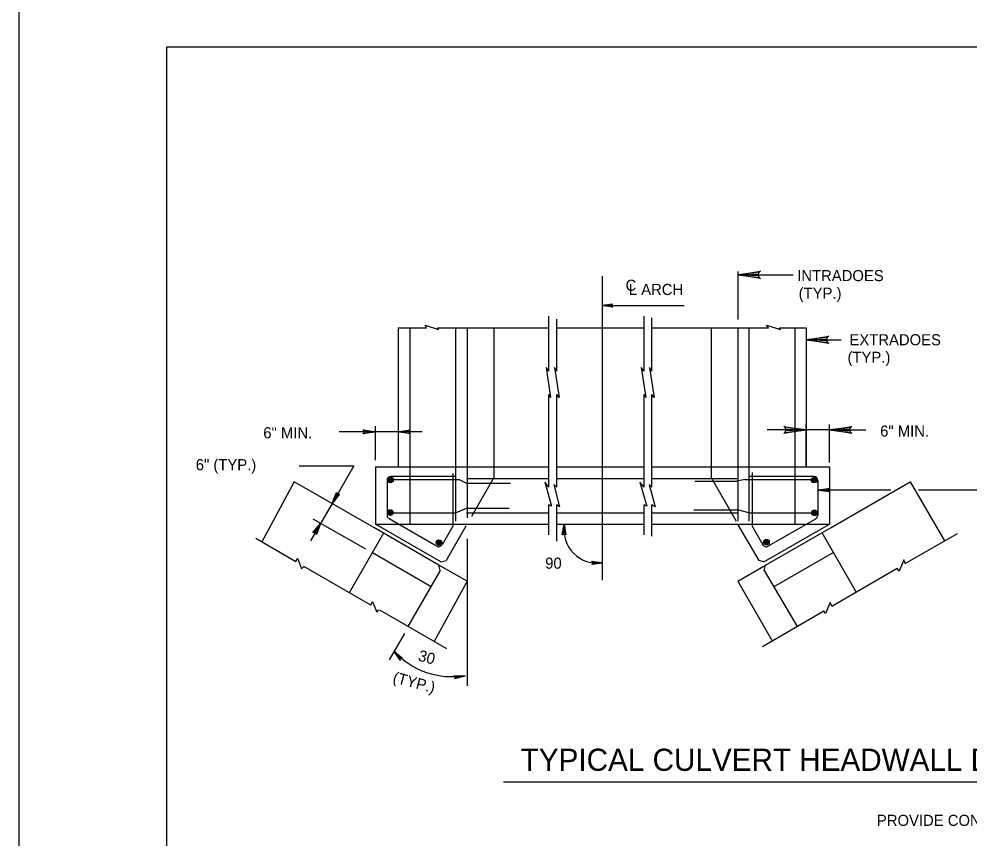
# Model space of a CAD drawing. Extents: x 639028 to 639883, y 298843 to 300031.
# Drawn here: x 639027.7 to 639285, y 299207.9 to 299429.6 of the extents above; entities that cross this region are included whole.
import ezdxf

# ---------------------------------------------------------------- set-up
doc = ezdxf.new("R2010")
doc.units = 0
for name, color, linetype in [('2', 7, 'Continuous'), ('52', 7, 'Continuous'), ('53', 7, 'Continuous'), ('PLT-BNDY', 7, 'Continuous')]:
    doc.layers.add(name, color=color, linetype=linetype)

msp = doc.modelspace()

# ---------------------------------------------------------------- linework, layer by layer
at = {"layer": '2'}
for p, q in [((639067.74, 298858.08), (639067.74, 299422.08)), ((639067.74, 299422.08), (639853.74, 299422.08)), ((639222.2, 299361.36), (639222.2, 299348.36)), ((639185.58, 299277.9), (639185.58, 299360.11)), ((639222.2, 299360.44), (639237.14, 299360.44)), ((639185.58, 299352.11), (639207.7, 299352.11)), ((639171.06, 299334.36), (639171.06, 299349.28)), ((639173.2, 299334.36), (639173.2, 299348.48)), ((639196.81, 299334.36), (639196.81, 299349.28)), ((639198.95, 299334.36), (639198.95, 299348.82)), ((639130.33, 299346.11), (639130.33, 299308.48)), ((639130.33, 299346.11), (639137.95, 299346.11)), ((639133.45, 299346.11), (639133.45, 299293.11)), ((639140.95, 299346.11), (639171.06, 299346.11)), ((639145.83, 299346.11), (639145.83, 299293.86)), ((639148.95, 299346.11), (639148.95, 299294.77)), ((639156.2, 299346.11), (639156.2, 299305.73)), ((639173.2, 299346.11), (639196.81, 299346.11)), ((639198.95, 299346.11), (639230.45, 299346.11)), ((639214.95, 299346.11), (639214.95, 299305.73)), ((639222.2, 299346.11), (639222.2, 299293.8)), ((639225.2, 299346.11), (639225.2, 299293.86)), ((639233.45, 299346.11), (639240.7, 299346.11)), ((639237.58, 299346.11), (639237.58, 299292.98)), ((639240.7, 299346.11), (639240.7, 299308.48)), ((639240.7, 299342.88), (639250.14, 299342.88)), ((639171.06, 299302.98), (639171.06, 299328.11)), ((639173.2, 299302.98), (639173.2, 299328.11)), ((639196.81, 299302.98), (639196.81, 299328.11)), ((639198.95, 299302.98), (639198.95, 299328.11)), ((639130.33, 299317.98), (639114.33, 299317.98)), ((639124.2, 299310.36), (639124.2, 299319.48)), ((639136.83, 299317.98), (639130.33, 299317.98)), ((639246.95, 299318.48), (639230.1, 299318.48)), ((639240.7, 299308.48), (639240.7, 299319.98)), ((639246.95, 299309.73), (639246.95, 299319.98)), ((639246.95, 299318.48), (639256.78, 299318.48)), ((639103.52, 299308.79), (639118.27, 299308.79)), ((639118.27, 299308.79), (639112.45, 299298.61)), ((639124.2, 299308.48), (639124.2, 299292.98)), ((639124.2, 299308.48), (639171.06, 299308.48)), ((639173.2, 299308.48), (639196.81, 299308.48)), ((639198.95, 299308.48), (639246.95, 299308.48)), ((639246.95, 299308.48), (639246.95, 299292.98)), ((639127.33, 299304.86), (639127.33, 299295.48)), ((639128.33, 299305.98), (639145.95, 299305.98)), ((639128.33, 299305.11), (639146.83, 299305.11)), ((639145.08, 299306.73), (639145.08, 299292.48)), ((639146.83, 299305.11), (639148.83, 299304.12)), ((639148.83, 299305.36), (639171.06, 299305.36)), ((639156.2, 299305.61), (639150.11, 299295.05)), ((639156.2, 299305.73), (639156.2, 299305.61)), ((639173.2, 299305.36), (639196.81, 299305.36)), ((639198.95, 299305.36), (639221.95, 299305.36)), ((639214.95, 299305.73), (639214.95, 299305.61)), ((639214.95, 299305.61), (639221.7, 299293.81)), ((639224.2, 299305.11), (639221.95, 299304.61)), ((639224.2, 299305.11), (639242.83, 299305.11)), ((639225.33, 299305.98), (639242.83, 299305.98)), ((639226.08, 299306.98), (639226.08, 299292.48)), ((639243.83, 299304.86), (639243.83, 299295.48)), ((639102.2, 299304.48), (639093.33, 299288.11)), ((639123.7, 299292.11), (639102.2, 299304.48)), ((639148.83, 299304.12), (639160.7, 299304.12)), ((639210.58, 299304.61), (639221.95, 299304.61)), ((639263.58, 299302.23), (639243.83, 299302.23)), ((639247.45, 299292.11), (639268.83, 299304.48)), ((639268.83, 299304.48), (639278.08, 299288.48)), ((639308.94, 299302.23), (639271.08, 299302.23)), ((639112.43, 299298.6), (639106.58, 299288.48)), ((639145.83, 299296.11), (639148.83, 299297.34)), ((639148.83, 299297.34), (639160.33, 299297.34)), ((639171.06, 299290.1), (639171.06, 299298.23)), ((639173.2, 299288.39), (639173.2, 299298.23)), ((639196.81, 299290.1), (639196.81, 299298.23)), ((639198.95, 299289.76), (639198.95, 299298.23)), ((639127.33, 299296.11), (639145.83, 299296.11)), ((639140.7, 299287.11), (639127.83, 299294.48)), ((639148.83, 299296.11), (639171.06, 299296.11)), ((639173.2, 299296.11), (639196.81, 299296.11)), ((639198.95, 299296.11), (639222.08, 299296.11)), ((639210.33, 299296.86), (639222.08, 299296.86)), ((639225.2, 299296.11), (639222.08, 299296.86)), ((639225.2, 299296.11), (639243.83, 299296.11)), ((639230.33, 299287.11), (639243.33, 299294.48)), ((639121.58, 299286.23), (639107.33, 299294.36)), ((639141.33, 299281.98), (639123.7, 299292.11)), ((639141.83, 299282.86), (639124.2, 299292.98)), ((639124.2, 299292.98), (639171.06, 299292.98)), ((639145.08, 299292.48), (639142.2, 299287.48)), ((639148.65, 299292.51), (639143.33, 299283.23)), ((639173.2, 299292.98), (639196.81, 299292.98)), ((639198.95, 299292.98), (639246.95, 299292.98)), ((639222.23, 299292.88), (639227.83, 299283.23)), ((639226.08, 299292.48), (639228.95, 299287.48)), ((639229.2, 299282.86), (639246.95, 299292.98)), ((639229.7, 299281.98), (639247.45, 299292.11)), ((639126.33, 299290.61), (639117.08, 299274.48)), ((639244.95, 299290.73), (639254.2, 299274.61)), ((639267.45, 299282.36), (639281.58, 299290.48)), ((639102.58, 299282.86), (639091.83, 299289.11)), ((639148.95, 299289.07), (639148.95, 299249.36)), ((639139.2, 299276.11), (639123.33, 299285.23)), ((639248.08, 299285.36), (639231.95, 299276.11)), ((639122.95, 299271.11), (639104.83, 299281.61)), ((639141.7, 299280.48), (639141.33, 299281.98)), ((639148.95, 299277.61), (639141.33, 299281.98)), ((639141.83, 299282.86), (639143.33, 299283.23)), ((639222.2, 299277.61), (639229.7, 299281.98)), ((639229.2, 299282.86), (639227.83, 299283.23)), ((639229.33, 299280.48), (639229.7, 299281.98)), ((639141.7, 299280.48), (639132.95, 299265.36)), ((639229.33, 299280.48), (639238.2, 299265.36)), ((639247.58, 299270.86), (639265.33, 299281.11)), ((639148.95, 299277.61), (639140.07, 299261.31)), ((639222.2, 299277.61), (639231.45, 299261.48)), ((639143.51, 299259.35), (639125.33, 299269.73)), ((639228.83, 299259.98), (639245.45, 299269.61)), ((639132.02, 299263.44), (639127.9, 299256.31))]:
    msp.add_line(p, q, dxfattribs=at)
for points in [[(639188.2, 299351.86), (639188.08, 299351.98), (639185.58, 299352.11), (639188.2, 299351.86), (639188.33, 299351.73), (639185.58, 299352.11), (639188.08, 299352.23), (639188.2, 299352.48), (639185.58, 299352.11), (639188.33, 299352.61), (639188.2, 299352.48)], [(639137.95, 299346.11), (639137.58, 299346.86), (639141.2, 299345.61), (639140.95, 299346.11)], [(639230.45, 299346.11), (639229.95, 299346.86), (639233.7, 299345.61), (639233.45, 299346.11)], [(639171.06, 299334.36), (639170.31, 299335.36), (639171.56, 299327.23), (639171.06, 299328.11)], [(639173.2, 299334.36), (639172.58, 299335.36), (639173.83, 299327.23), (639173.2, 299328.11)], [(639196.81, 299334.36), (639196.06, 299335.36), (639197.31, 299327.23), (639196.81, 299328.11)], [(639198.95, 299334.36), (639198.33, 299335.36), (639199.58, 299327.23), (639198.95, 299328.11)], [(639120.95, 299318.36), (639121.08, 299318.11), (639124.2, 299317.98), (639120.95, 299318.36), (639120.83, 299318.48), (639124.2, 299317.98), (639121.08, 299317.86), (639120.95, 299317.61), (639124.2, 299317.98), (639120.83, 299317.48), (639120.95, 299317.61)], [(639121.08, 299318.36), (639121.2, 299318.11), (639124.2, 299317.98), (639121.08, 299318.36), (639120.95, 299318.48), (639124.2, 299317.98), (639121.2, 299317.86), (639121.2, 299317.61), (639124.2, 299317.98), (639120.95, 299317.48), (639121.2, 299317.61)], [(639133.45, 299317.61), (639133.33, 299317.86), (639130.33, 299317.98), (639133.45, 299317.61), (639133.58, 299317.48), (639130.33, 299317.98), (639133.33, 299318.11), (639133.33, 299318.36), (639130.33, 299317.98), (639133.58, 299318.48), (639133.33, 299318.36)], [(639133.45, 299317.61), (639133.33, 299317.86), (639130.33, 299317.98), (639133.45, 299317.61), (639133.58, 299317.48), (639130.33, 299317.98), (639133.33, 299318.11), (639133.33, 299318.36), (639130.33, 299317.98), (639133.58, 299318.48), (639133.33, 299318.36)], [(639237.45, 299318.86), (639237.58, 299318.61), (639240.7, 299318.48), (639237.45, 299318.86), (639237.33, 299318.98), (639240.7, 299318.48), (639237.58, 299318.36), (639237.45, 299318.11), (639240.7, 299318.48), (639237.33, 299317.98), (639237.45, 299318.11)], [(639237.45, 299318.86), (639237.58, 299318.61), (639240.7, 299318.48), (639237.45, 299318.86), (639237.33, 299318.98), (639240.7, 299318.48), (639237.58, 299318.36), (639237.45, 299318.11), (639240.7, 299318.48), (639237.33, 299317.98), (639237.45, 299318.11)], [(639250.2, 299318.11), (639250.08, 299318.36), (639246.95, 299318.48), (639250.2, 299318.11), (639250.33, 299317.98), (639246.95, 299318.48), (639250.08, 299318.61), (639250.2, 299318.86), (639246.95, 299318.48), (639250.33, 299318.98), (639250.2, 299318.86)], [(639171.06, 299302.98), (639169.94, 299304.36), (639171.81, 299297.86), (639171.06, 299298.23)], [(639173.2, 299302.98), (639172.45, 299303.73), (639173.95, 299297.73), (639173.2, 299298.23)], [(639196.81, 299302.98), (639195.69, 299304.36), (639197.56, 299297.86), (639196.81, 299298.23)], [(639198.95, 299302.98), (639198.2, 299303.73), (639199.83, 299297.73), (639198.95, 299298.23)], [(639246.95, 299301.86), (639246.83, 299302.11), (639243.83, 299302.23), (639246.95, 299301.86), (639247.08, 299301.73), (639243.83, 299302.23), (639246.83, 299302.36), (639246.83, 299302.61), (639243.83, 299302.23), (639247.08, 299302.73), (639246.83, 299302.61)], [(639114.33, 299301.11), (639114.08, 299301.11), (639112.45, 299298.61), (639114.33, 299301.11), (639114.45, 299301.11), (639112.45, 299298.61), (639113.83, 299301.23), (639113.7, 299301.48), (639112.45, 299298.61), (639113.58, 299301.61), (639113.7, 299301.48)], [(639114.33, 299301.11), (639114.08, 299301.11), (639112.45, 299298.61), (639114.33, 299301.11), (639114.45, 299301.11), (639112.45, 299298.61), (639113.83, 299301.23), (639113.7, 299301.48), (639112.45, 299298.61), (639113.58, 299301.61), (639113.7, 299301.48)], [(639107.45, 299290.73), (639107.7, 299290.73), (639109.33, 299293.23), (639107.45, 299290.73), (639107.2, 299290.73), (639109.33, 299293.23), (639107.95, 299290.61), (639108.08, 299290.36), (639109.33, 299293.23), (639108.2, 299290.23), (639108.08, 299290.36)], [(639174.83, 299290.23), (639175.08, 299290.36), (639175.2, 299293.11), (639174.83, 299290.23), (639174.7, 299290.11), (639175.2, 299293.11), (639175.33, 299290.36), (639175.58, 299290.23), (639175.2, 299293.11), (639175.7, 299290.11), (639175.58, 299290.23)], [(639102.58, 299282.86), (639103.08, 299283.86), (639104.2, 299280.98), (639104.83, 299281.61)], [(639182.83, 299282.86), (639182.95, 299282.73), (639185.58, 299282.61), (639182.83, 299282.86), (639182.7, 299282.98), (639185.58, 299282.61), (639182.95, 299282.36), (639182.83, 299282.23), (639185.58, 299282.61), (639182.7, 299282.11), (639182.83, 299282.23)], [(639267.45, 299282.36), (639267.08, 299283.36), (639265.83, 299280.36), (639265.33, 299281.11)], [(639122.95, 299271.11), (639123.33, 299272.11), (639124.58, 299269.23), (639125.08, 299269.86)], [(639247.58, 299270.86), (639247.2, 299271.86), (639245.95, 299268.86), (639245.45, 299269.61)], [(639130.77, 299256.31), (639130.9, 299256.56), (639129.15, 299258.69), (639130.77, 299256.31), (639130.9, 299256.19), (639129.15, 299258.69), (639131.15, 299256.81), (639131.27, 299256.81), (639129.15, 299258.69), (639131.52, 299256.81), (639131.27, 299256.81)], [(639145.65, 299251.94), (639145.77, 299251.81), (639148.4, 299252.06), (639145.65, 299251.94), (639145.4, 299252.06), (639148.4, 299252.06), (639145.77, 299251.56), (639145.65, 299251.31), (639148.4, 299252.06), (639145.52, 299251.19), (639145.65, 299251.31)]]:
    msp.add_lwpolyline(points, dxfattribs=at)
for centre, radius in [((639128.21, 299305), 0.763), ((639128.21, 299305), 0.545), ((639128.21, 299305), 0.298), ((639128.21, 299305), 0.15), ((639128.21, 299305), 0.0644), ((639242.83, 299304.96), 0.763), ((639242.83, 299304.96), 0.545), ((639242.83, 299304.96), 0.298), ((639242.83, 299304.96), 0.15), ((639242.83, 299304.96), 0.0644), ((639128.19, 299296.15), 0.763), ((639128.19, 299296.15), 0.545), ((639128.19, 299296.15), 0.298), ((639128.19, 299296.15), 0.15), ((639128.19, 299296.15), 0.0644), ((639242.93, 299296.09), 0.763), ((639242.93, 299296.09), 0.545), ((639242.93, 299296.09), 0.298), ((639242.93, 299296.09), 0.15), ((639242.93, 299296.09), 0.0644), ((639141.34, 299288.03), 0.763), ((639141.34, 299288.03), 0.545), ((639141.34, 299288.03), 0.298), ((639141.34, 299288.03), 0.15), ((639141.34, 299288.03), 0.0644), ((639229.94, 299288.14), 0.763), ((639229.94, 299288.14), 0.545), ((639229.94, 299288.14), 0.298), ((639229.94, 299288.14), 0.15), ((639229.94, 299288.14), 0.0644)]:
    msp.add_circle(centre, radius, dxfattribs=at)
for centre, radius, start, end in [((639128.32, 299304.9), 1.03, 90, 180), ((639242.79, 299304.9), 1.03, 0, 90), ((639128.32, 299295.43), 1.03, 180, 239.9948), ((639242.79, 299295.43), 1.03, 300.0021, 0), ((639184.26, 299291.62), 9.17, 170.9433, 278.4783), ((639141.25, 299287.96), 1.03, 239.9957, 330.0037), ((639229.86, 299287.96), 1.03, 209.9963, 300.0011), ((639144.92, 299273.31), 21.51, 222.9112, 279.3964)]:
    msp.add_arc(centre, radius, start, end, dxfattribs=at)
at = {"layer": '52'}
for points in [[(639228, 299359.72), (639227.79, 299360.14), (639222.2, 299360.44), (639228, 299359.72), (639228.3, 299359.46), (639222.2, 299360.44), (639227.78, 299360.72), (639227.99, 299361.13), (639222.2, 299360.44), (639228.3, 299361.41), (639227.99, 299361.13)], [(639246.5, 299342.16), (639246.29, 299342.58), (639240.7, 299342.88), (639246.5, 299342.16), (639246.8, 299341.9), (639240.7, 299342.88), (639246.28, 299343.16), (639246.49, 299343.58), (639240.7, 299342.88), (639246.8, 299343.85), (639246.49, 299343.58)], [(639234.9, 299319.21), (639235.12, 299318.79), (639240.7, 299318.48), (639234.9, 299319.21), (639234.61, 299319.47), (639240.7, 299318.48), (639235.13, 299318.21), (639234.92, 299317.79), (639240.7, 299318.48), (639234.61, 299317.51), (639234.92, 299317.79)], [(639252.75, 299317.76), (639252.54, 299318.18), (639246.95, 299318.48), (639252.75, 299317.76), (639253.05, 299317.5), (639246.95, 299318.48), (639252.53, 299318.76), (639252.74, 299319.17), (639246.95, 299318.48), (639253.05, 299319.45), (639252.74, 299319.17)]]:
    msp.add_lwpolyline(points, dxfattribs=at)
at = {"layer": '53'}
msp.add_line((639158.78, 299223.33), (639487.83, 299223.33), dxfattribs=at)
at = {"layer": 'PLT-BNDY'}
msp.add_lwpolyline([(639027.74, 299437.08), (639868.74, 299437.08), (639868.74, 298843.08), (639027.74, 298843.08)], close=True, dxfattribs=at)

# ---------------------------------------------------------------- texts
at = {"layer": '2'}
for s, p in [('INTRADOES', (639238.25, 299358.72)), ('C', (639191.83, 299356.11)), ('L ARCH', (639192.7, 299354.98)), ('(TYP.)', (639238.65, 299353.97)), ('EXTRADOES', (639252.39, 299341.38)), ('(TYP.)', (639251.87, 299336.64)), ('6" MIN. ', (639093.82, 299316.23)), ('6" MIN. ', (639260.69, 299316.7)), ('6" (TYP.)', (639075.55, 299307.6)), ('90', (639170.08, 299280.98)), ('PROVIDE CONCRETE APRON AT INLET AND OUTLET.', (639259.81, 299211.45))]:
    msp.add_text(s, height=3, dxfattribs=at).set_placement(p)
for s, p in [('30', (639135.52, 299256.19)), ('(TYP.)', (639128.65, 299250.31))]:
    msp.add_text(s, height=3, rotation=345, dxfattribs=at).set_placement(p)
at = {"layer": '53'}
msp.add_text('TYPICAL CULVERT HEADWALL DETAILS - FIXED AND TIED ARCH', height=6, dxfattribs=at).set_placement((639163.46, 299226.33))

doc.saveas('drawing.dxf')
